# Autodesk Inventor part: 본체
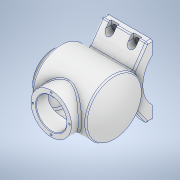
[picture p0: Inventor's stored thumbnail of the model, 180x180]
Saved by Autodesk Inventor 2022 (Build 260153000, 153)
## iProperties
Created: 2023-04
Part Number: 본체
Material: 알루미늄 6061
Document SubType Name: Modeling
Designer: Admin
Mass: 1299.42 g
Surface Area: 1060.79 cm^2
Volume: 481.266 cm^3
Density: 2.7 g/cm^3
Appearance: 알루미늄 - 평지
Author: Admin
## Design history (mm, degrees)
sketch "스케치1"
  geometry: L1 (0, 27)-(19, 27); L2 (19, 27)-(19, 43); L3 (19, 43)-(103.887, 43); L4 (0, 27)-(0, 36); L5 (0, 36)-(12, 36); L6 (12, 36)-(12, 50); L7 (12, 50)-(108.336, 50); L8 (-24.575, 0)-(147.453, 0) reference; L9 (0, -10.134)-(0, 60.805) reference; L10 (113, 0)-(120, 0); A1 r 106 centre (7, 0) between (113, 0) and (103.887, 43); A2 r 113 centre (7, 0) between (120, 0) and (108.336, 50); 2 further points
  constraints: 16 end point, 5 perpendicular, 4 point on circle, 4 point on line, 2 centre point, 1 coincident, 1 collinear, 1 horizontal, 1 midpoint, 1 vertical
  dimensions: "d0" = 113 radius of A2; "d1" = 7 radial gap between concentric circles of A2 A1; "d2" = 120 horizontal distance of L10.end L4.end; "d3" = 108 horizontal distance of L10.end L6.end; "d4" = 54 diameter of L1 L8; "d5" = 86 diameter of L3 L8; "d6" = 100 diameter of L7 L8; "d7" = 72 diameter of L5 L8; "d8" = 19 distance of L1.start L1.end
revolve "회전1" sketch "스케치1" stored, may be unused: angle "d9" = 90 deg
node "작업 평면1"
sketch "스케치2"
  geometry: L1 (0, -70)-(0, 70) reference; L2 (-70, 0)-(70, 0) reference; L3 (26.694, -42.278)-(62, -67); L4 (62, -67)-(62, -77); L5 (62, -77)-(38.5, -77); L6 (-26.694, -42.278)-(-62, -67); L7 (-62, -67)-(-62, -77); L8 (-62, -77)-(-38.5, -77); A1 r 52.096 centre (0, -112.096) between (38.5, -77) and (-38.5, -77); 4 further points
  constraints: 12 end point, 4 symmetric about line, 3 point on circle, 2 vertical, 1 centre point, 1 perpendicular, 1 point on line, 5 other
  dimensions: "d11" = 10 distance of L3.end L4.end; "d12" = 55 deg angle of L3 L4; "d13" = 77 distance of L8.end L5.end; "d14" = 17 distance from line of L8 point (0, -60); "d15" = 77 distance between parallel lines of L8 L2; "d16" = 124 distance between parallel lines of L7 L4
extrude "돌출1" join sketch "스케치2" distance "d17" = 80; taper "d18" = 0 deg
node "작업 평면3"
sketch "스케치3"
  geometry: L1 (20, 38.5)-(20, 62) reference; L2 (20, 62)-(100, 62) reference; L3 (100, 38.5)-(100, 62) reference; L4 (20, 38.5)-(100, 38.5) reference; L5 (20, -62)-(20, -38.5) reference; L6 (20, -38.5)-(100, -38.5) reference; L7 (100, -62)-(100, -38.5) reference; L8 (20, -62)-(100, -62) reference; L9 (0, -86.8)-(0, 86.8) reference; L10 (-24, 0)-(144, 0) reference; L11 (87, -54)-(87, -62); L12 (20, -62)-(100, -62) reference; L13 (73, -54)-(73, -62); L14 (47, -54)-(47, -62); L15 (33, -54)-(33, -62); A1 r 7 centre (80, -54) between (87, -54) and (73, -54); A2 r 7 centre (40, -54) between (47, -54) and (33, -54); 3 further points
  constraints: 8 end point, 4 point on circle, 4 point on line, 4 tangent, 3 perpendicular, 2 centre point, 2 coincident, 1 horizontal alignment, 1 vertical
  dimensions: "d20" = 20 distance from line of point (80, -54) L7; "d21" = 40 distance of point (40, -54) point (80, -54); "d22" = 8 distance from line of L8 point (80, -54); "d23" = 14 diameter of A1; "d24" = 14 diameter of A2
extrude "돌출2" cut sketch "스케치3" stored distance "d25" = 80; taper "d26" = 0 deg
sketch "스케치4"
  geometry: C1 r 4.5 at (40, -54); C2 r 4.5 at (80, -54); A1 r 7 centre (40, -54) between (47, -54) and (33, -54) reference; A2 r 7 centre (80, -54) between (87, -54) and (73, -54) reference; 1 further point
  constraints: 2 centre point, 2 coincident
  dimensions: "d27" = 9 diameter of C1; "d28" = 9 diameter of C2
extrude "돌출3" cut sketch "스케치4" extent not by distance; stored distance "d29" = 0; taper "d30" = 0 deg
node "작업 평면4"
sketch "스케치5"
  geometry: L1 (0, -70)-(0, 70) reference; L2 (-24, 0)-(144, 0) reference; C1 r 36 at (62, 0); 1 further point
  constraints: 1 centre point, 1 point on line
  dimensions: "d32" = 72 diameter of C1; "d33" = 62 distance from line of L1 C1.centre
extrude "돌출4" join sketch "스케치5" stored distance "d34" = 10; taper "d35" = 0 deg
sketch "스케치6"
  geometry: L1 (-86, 0)-(82, 0) reference; L2 (-62, -86.8)-(-62, 86.8) reference; C1 r 36 at (0, 0) reference; C2 r 27 at (0, 0); 1 further point
  constraints: 1 centre point, 1 coincident
  dimensions: "d36" = 54 diameter of C2
extrude "돌출5" cut sketch "스케치6" stored distance "d37" = 10; taper "d38" = 0 deg
sketch "스케치7" dims "d39" = 65
  geometry: L1 (-70, 0)-(70, 0) reference; C1 r 27 at (0, 0) reference; C2 r 36 at (0, 0) reference; 3 further points
  constraints: 1 coincident, 1 horizontal alignment, 1 point on line, 2 other
hole "구멍1" sketch "스케치7" at (32.5, 0) diameter "d40" = 3.242; stored, may be unused: countersink angle "d44" = 90 deg, drill point angle "d46" = 118 deg; dims "d41" = 8, "d42" = 4, "d43" = 2, "d45" = 10
sketch "스케치8" dims "d50" = 65
  geometry: L1 (-86, 0)-(82, 0) reference; C1 r 27 at (0, 0) reference; C2 r 36 at (0, 0) reference; 3 further points
  constraints: 1 coincident, 1 horizontal alignment, 1 point on line, 2 other
hole "구멍2" sketch "스케치8" at (32.5, 0) diameter "d51" = 3.242; stored, may be unused: countersink angle "d55" = 90 deg, drill point angle "d57" = 118 deg; dims "d52" = 8, "d53" = 4, "d54" = 2, "d56" = 10
node "작업 평면5"
sketch "스케치9"
  geometry: L1 (-60.168, -36)-(-60.168, 36) reference; L2 (-84.168, 0)-(83.832, 0) reference; 2 further points
  constraints: 1 point on line, 1 other
  dimensions: "d62" = 62 distance from line of point (1.832, 0) L1
feature "엠보싱1" sketch "스케치9" dims "d0" = 113, "d1" = 7, "d2" = 120, "d3" = 108, "d4" = 54, "d5" = 86, "d6" = 100, "d7" = 72, "d8" = 19, "d63" = 0.5, "d64" = 0
fillet "모깎기1" dims "d65" = 3
chamfer "모따기1" distance "d66" = 1; stored, may be unused: second distance "d67" = 2, angle "d68" = 45 deg
node "솔리드1"
mirror "미러1"
pattern_circular "원형 패턴1" dims angle "d48" = 360 deg
pattern_circular "원형 패턴2" dims angle "d59" = 360 deg
node "투영된 루프1"
node "투영된 루프2"
node "투영된 루프3"
node "투영된 루프4"
node "투영된 루프5"
feature "A9D066F2-1C7D-4E18-AEED-F7BC21143FA4" dims "d40" = 3.242, "d41" = 8, "d42" = 4, "d43" = 2, "d44" = 90 deg, "d45" = 10, "d46" = 118 deg
other parameters: "d19" = -71, "d31" = 65
